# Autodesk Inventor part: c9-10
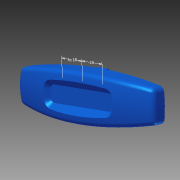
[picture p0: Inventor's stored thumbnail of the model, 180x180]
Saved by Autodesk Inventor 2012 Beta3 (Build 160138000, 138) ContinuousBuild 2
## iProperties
Created: 2010-12
Part Number: c9-10
Material: Default
Document SubType Name: Modeling
Designer: Beta-8540w
Density: 1 g/cm^3
Author: Beta-8540w
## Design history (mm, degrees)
sketch "Sketch1"
  geometry: L1 (-60, -12)-(60, -12); L2 (60, -12)-(60, 12); L3 (60, 12)-(-60, 12); L4 (-60, 12)-(-60, -12); A1 r 350 centre (0, -332.819) between (60, 12) and (-60, 12); A2 r 350 centre (0, 332.819) between (-60, -12) and (60, -12); 3 further points
  constraints: 8 end point, 4 point on circle, 2 centre point, 2 midpoint, 2 parallel, 1 equal radius, 1 horizontal, 1 horizontal alignment, 1 perpendicular, 1 vertical alignment
  dimensions: "d0" = 120 distance of L3.end L2.end; "d1" = 24 distance of L2.end L1.end; "d2" = 350 radius of A1
workplane "Work Plane4"
sketch "Sketch5"
  geometry: L1 (-60, 12)-(-60, -12) reference; L2 (60, -12)-(60, 12) reference; L3 (-58, 10.314)-(-58, -10.314); L4 (58, -10.314)-(58, 10.314); A1 r 350 centre (0, 332.819) between (-60, -12) and (60, -12) reference; A2 r 350 centre (0, -332.819) between (60, 12) and (-60, 12) reference; A3 r 348 centre (0, 332.819) between (-58, -10.314) and (58, -10.314); A4 r 348 centre (0, -332.819) between (58, 10.314) and (-58, 10.314); 1 further point
  constraints: 4 end point, 4 point on circle, 2 centre point, 3 other
  dimensions: "d37" = 2 distance between parallel lines of L2 L4
sketch "Sketch6"
  geometry: L1 (-60, 0)-(60, 0); L2 (60, 0)-(58.843, 22.085); L3 (-60, 0)-(-58.779, 23.307); A1 r 691.758 centre (630.81, -36.204) between (-60, 0) and (-58, -100); A2 r 691.758 centre (-630.81, -36.204) between (58, -100) and (60, 0); 1 further point
  constraints: 6 end point, 4 point on circle, 2 centre point, 2 tangent, 1 horizontal
  dimensions: "d53" = 87 deg angle of L1 L3; "d54" = 87 deg angle of L1 L2 (= d53)
sketch "Sketch7"
  geometry: L1 (17.181, 0)-(12, 0) reference; L2 (15.181, -100)-(10.314, -100) reference; L3 (17.181, 0)-(16.768, 11.838); A1 r 911.322 centre (-893.585, -31.805) between (15.181, -100) and (17.181, 0); 1 further point
  constraints: 2 end point, 2 point on circle, 1 centre point, 1 tangent
  dimensions: "d56" = 88 deg angle of L1 L3
feature "LoftSrf2" sketch "Sketch5", "Sketch6", "Sketch7" dims "d57" = 0, "d58" = 90 deg, "d59" = 0, "d60" = 90 deg, "d61" = 0, "d62" = 90 deg, "d63" = 0, "d64" = 90 deg, "d65" = 0, "d66" = 90 deg
sketch "Sketch2"
  geometry: L1 (-75, -16)-(75, -16); L2 (-75, -60)-(75, -60); A1 r 183.781 centre (0, -183.781) between (75, -16) and (-75, -16); 2 further points
  constraints: 4 end point, 3 point on circle, 1 centre point, 1 coincident, 1 horizontal, 1 parallel
  dimensions: "d5" = 16 distance from line of point (0, 0) L1; "d7" = 60 distance from line of point (0, 0) L2; "d55" = 150 distance of L1.start L1.end
feature "RevolutionSrf1" sketch "Sketch2" dims angle "d8" = 40 deg
patch "Boundary Patch1" dims "d13" = 0, "d67" = 0, "d68" = 0, "d69" = 0, "d70" = 0
workplane "Work Plane1"
sketch "Sketch3"
  geometry: L1 (52, -85)-(52, -73); L2 (38, -73)-(38, -85); A1 r 7 centre (45, -73) between (52, -73) and (38, -73); A2 r 7 centre (45, -85) between (38, -85) and (52, -85); 1 further point
  constraints: 4 end point, 4 point on circle, 4 tangent, 2 centre point, 1 parallel, 1 vertical
  dimensions: "d15" = 12 distance of L1.start L1.end; "d16" = 7 radius of A1; "d50" = 45 horizontal distance of A1.centre point (0, 0); "d51" = 85 vertical distance of point (0, 0) A2.centre
extrude_surface "ExtrusionSrf2" sketch "Sketch3" dims "d19" = 14, "d20" = 5 deg
pattern_linear "Rectangular Pattern1" dims "d23" = 90
workplane "Work Plane2"
feature "Sculpt1"
sketch "Sketch4"
  geometry: L1 (-24.5, 6)-(24.5, 6); L2 (27.5, 3)-(27.5, -3); L3 (24.5, -6)-(-24.5, -6); L4 (-27.5, -3)-(-27.5, 3); A1 r 3 centre (-24.5, 3) between (-24.5, 6) and (-27.5, 3); A2 r 3 centre (24.5, 3) between (27.5, 3) and (24.5, 6); A3 r 3 centre (24.5, -3) between (24.5, -6) and (27.5, -3); A4 r 3 centre (-24.5, -3) between (-27.5, -3) and (-24.5, -6); 6 further points
  constraints: 8 end point, 8 point on circle, 8 tangent, 6 point on line, 4 centre point, 3 equal radius, 2 midpoint, 2 parallel, 1 horizontal, 1 horizontal alignment, 1 perpendicular, 1 vertical alignment
  dimensions: "d28" = 55 distance of point (27.5, -6) point (-27.5, -6); "d29" = 12 distance of point (27.5, 6) point (27.5, -6); "d30" = 3 radius of A1
extrude_surface "ExtrusionSrf6" sketch "Sketch4" dims "d31" = 14, "d32" = 45 deg
patch "Boundary Patch2" dims "d33" = 0, "d34" = 0
fillet "Fillet1" dims "d79" = 4, "d80" = 3, "d81" = 1
feature "Sculpt2"
node "Splitting Plane 1"
shell "Shell1" dims "d83" = 2
split "Split1"
  body "Solid1"
feature "Lip1" dims "d188" = 1, "d189" = 1, "d190" = 0, "d191" = 0, "d192" = 0, "d193" = 0
feature "Lip2" dims "d194" = 1, "d195" = 1, "d196" = 0, "d197" = 0, "d198" = 0, "d199" = 0.5
split "Split3"
  node "Back"
sketch "Sketch9"
  geometry: L1 (50.167, -73)-(50.167, -85) reference; L2 (39.833, -85)-(39.833, -73) reference; L3 (45, -73)-(45, -85); L4 (45, -85)-(39.833, -85); A1 r 5.167 centre (45, -73) between (50.167, -73) and (39.833, -73) reference; A2 r 5.167 centre (45, -85) between (39.833, -85) and (50.167, -85) reference; 5 further points
  constraints: 4 end point, 1 horizontal, 1 midpoint, 1 parallel, 1 perpendicular, 1 vertical, 3 other
  dimensions: "d86" = 90 distance of point (45, -79) point (-45, -79); "d89" = 40 distance of point (45, -79) point (45, -39)
  node "Projected Loop1"
feature "Boss1" dims "d92" = 0, "d93" = 0, "d94" = 7, "d95" = 2, "d96" = 0.5, "d97" = 6, "d98" = 1.25, "d99" = 3.5, "d100" = 2.5 deg, "d101" = 2.5 deg, "d102" = 2.5 deg, "d103" = 2.5 deg, "d104" = 90 deg, "d107" = 2, "d108" = 2, "d109" = 10, "d110" = 0, "d111" = 10 deg, "d112" = 2.5 deg, "d113" = 0, "d114" = 0, "d115" = 0, "d116" = 360 deg
feature "Boss2" dims "d117" = 3, "d118" = 0, "d119" = 6, "d120" = 3, "d121" = 9.5, "d122" = 2 deg, "d123" = 1 deg, "d126" = 2, "d127" = 2, "d128" = 10, "d129" = 0, "d130" = 10 deg, "d131" = 2.5 deg, "d132" = 0, "d133" = 0, "d134" = 0, "d135" = 360 deg
workplane "Work Plane6"
sketch "Sketch10"
  geometry: L1 (24, -85)-(-24, -85); L2 (-30, -79)-(-30, -51); L3 (-24, -45)-(24, -45); L4 (30, -51)-(30, -79); L5 (54.344, -100)-(-54.344, -100) reference; A1 r 6 centre (-24, -51) between (-24, -45) and (-30, -51); A2 r 6 centre (24, -51) between (30, -51) and (24, -45); A3 r 6 centre (24, -79) between (24, -85) and (30, -79); A4 r 6 centre (-24, -79) between (-30, -79) and (-24, -85); 5 further points
  constraints: 8 end point, 8 point on circle, 8 tangent, 6 point on line, 4 centre point, 3 equal radius, 2 parallel, 1 horizontal, 1 midpoint, 1 perpendicular, 1 vertical alignment
  dimensions: "d137" = 60 distance of point (-30, -45) point (30, -45); "d138" = 40 distance of point (-30, -85) point (-30, -45); "d139" = 15 distance between parallel lines of L5 L1; "d141" = 6 radius of A2
feature "Rest1" sketch "Sketch10" dims "d142" = 5, "d143" = 0, "d144" = 0, "d145" = 0, "d146" = 2 deg, "d147" = 2 deg, "d148" = 2
feature "Rule Fillet1" dims "d149" = 2, "d150" = 1
workplane "Work Plane7"
sketch "Sketch11" dims "d154" = 16, "d155" = 8, "d161" = 10, "d168" = 10
  geometry: L1 (-13, -39.858)-(-13, -90.142); L2 (-25.187, -85)-(29.449, -85); L3 (0, -39.858)-(0, -90.142); L4 (13, -39.858)-(13, -90.142); L5 (-25.187, -77)-(29.449, -77); L6 (-25.187, -69)-(29.449, -69); L7 (-25.187, -61)-(29.449, -61); L8 (-25.187, -53)-(29.449, -53); L9 (-25.187, -45)-(29.449, -45); C1 r 22.5 at (0, -65); 3 further points; 1 other entity
  constraints: 18 end point, 2 coincident, 2 vertical, 1 centre point, 1 horizontal, 1 midpoint, 1 perpendicular, 1 vertical alignment, 23 other
  dimensions: "d152" = 45 diameter of C1; "d153" = 65 distance of point (0, 0) C1.centre; "d158" = 13 distance of L1.start L3.start; "d165" = 8 distance of L2.start L5.start; "d170" = 4 distance from line of L7 point (0, -65)
feature "Grill1" sketch "Sketch11" dims "d173" = 2, "d174" = 0, "d175" = 1, "d176" = 2, "d177" = 0, "d178" = 1, "d179" = 0.5, "d180" = 0, "d181" = 2, "d182" = 1, "d183" = 2 deg, "d184" = 0, "d185" = 88.84492
sketch "Sketch12"
  geometry: L1 (-12.481, -61.203)-(12.401, -61.203); L2 (12.401, -61.203)-(12.401, -68.714); L3 (12.401, -68.714)-(-12.481, -68.714); L4 (-12.481, -68.714)-(-12.481, -61.203); 1 further point
  constraints: 2 other
emboss "Emboss1" sketch "Sketch12" dims "d186" = 0.5, "d187" = 0
sketch "Sketch13"
  geometry: L1 (0, 15.66)-(0, -14.781); 6 further points
  constraints: 2 end point, 1 coincident, 1 point on line, 1 vertical, 4 other
feature "Snap Fit1" sketch "Sketch13" dims "d200" = 4, "d201" = 2.5, "d202" = 1, "d203" = 0.9, "d204" = 10.2, "d205" = 10, "d206" = 1, "d207" = 1, "d208" = 50 deg, "d209" = 50 deg
fillet "Fillet2" dims "d213" = 2
workplane "Work Plane8"
sketch "Sketch14"
  geometry: L1 (-8.644, -6.828)-(57.644, -6.828); L2 (6.5, 3.689)-(6.5, -17.346); L3 (24.5, 3.689)-(24.5, -17.346); L4 (42.5, 3.689)-(42.5, -17.346); 2 further points
  constraints: 8 end point, 4 parallel, 2 horizontal alignment, 2 midpoint, 1 coincident, 1 horizontal, 1 perpendicular
  dimensions: "d211" = 18 distance between parallel lines of L3 L2; "d212" = 18 distance between parallel lines of L4 L3 (= d211)
body "Srf2"
body "Srf3"
body "Srf4"
body "Srf5"
body "Srf6"
body "Srf7"
body "Srf8"
body "Srf9"
body "Srf11"
feature "Stitch Surface1"
body "Srf12"
extrude_surface "ExtrusionSrf3"
extrude_surface "ExtrusionSrf4"
extrude_surface "ExtrusionSrf5"
node "Front"
node "Back - Top"
node "Back - Bottom"
other parameters: "d14" = -24, "d52" = -6, "d171" = 1, "d172" = 2, "d210" = -1
